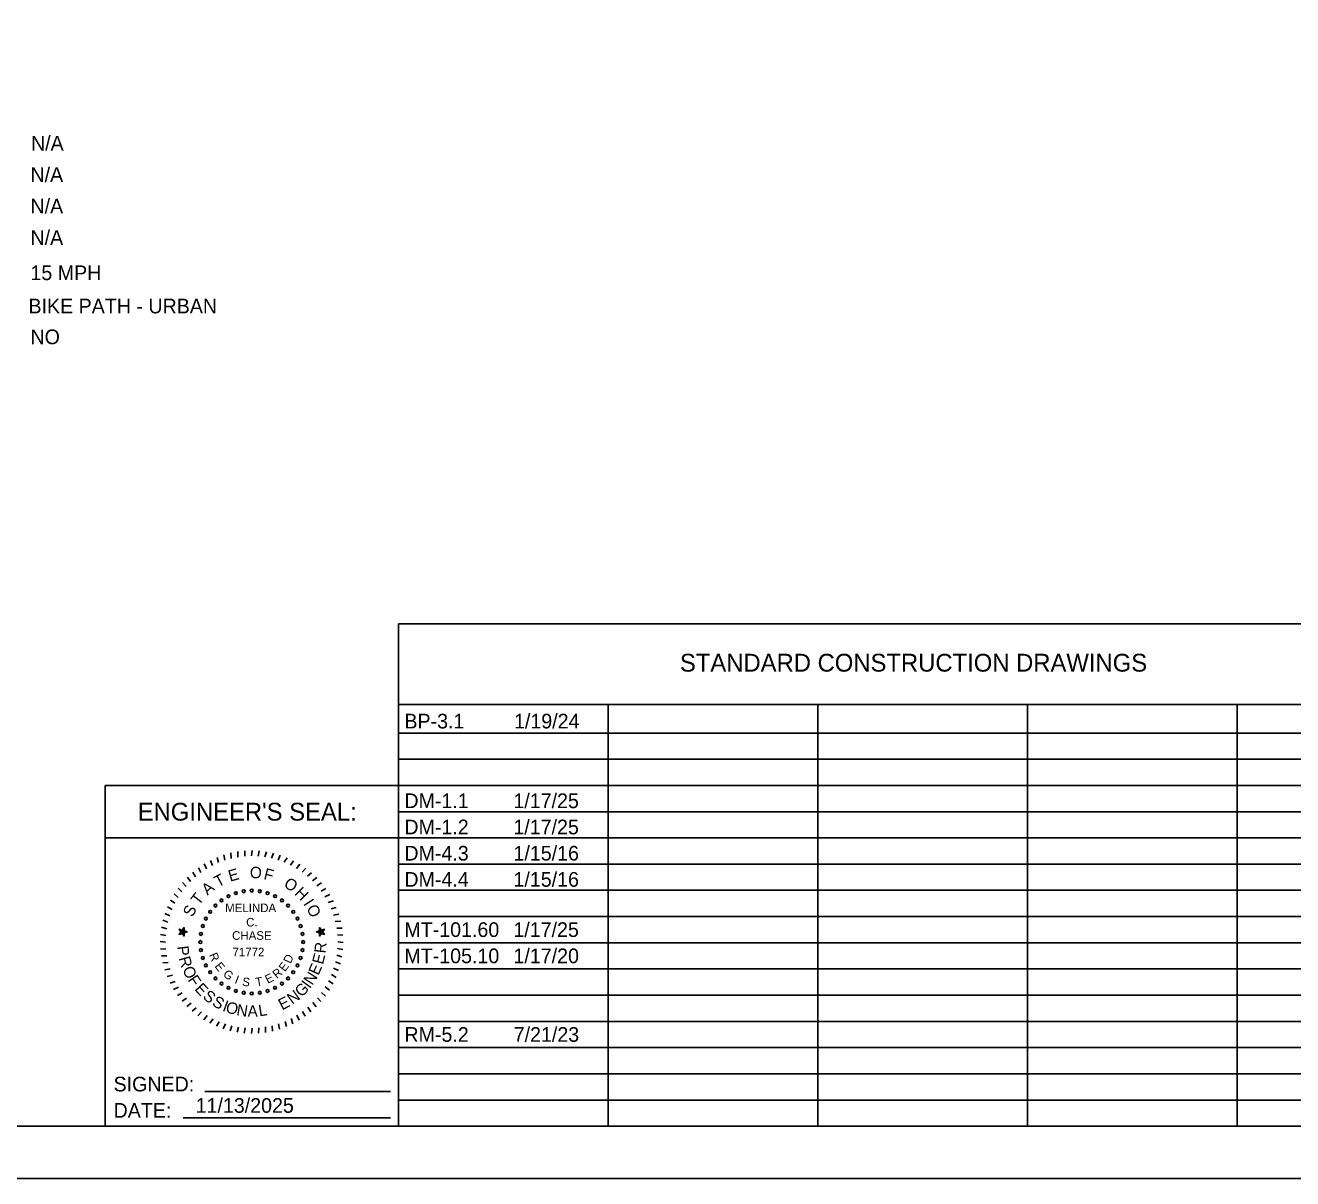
# Model space of a CAD drawing. Extents: x 0 to 34, y 0 to 22.
# Drawn here: x 7.69 to 19.78, y 0 to 11 of the extents above; entities that cross this region are included whole.
import ezdxf

# ---------------------------------------------------------------- set-up
doc = ezdxf.new("R2010")
doc.units = 0
for name, color, linetype in [('Default', 7, 'Continuous'), ('GM_X_Adjacent_County', 7, 'Continuous'), ('GM_X_County', 7, 'Continuous'), ('GM_X_Section', 7, 'Continuous'), ('GM_X_Township', 7, 'Continuous')]:
    doc.layers.add(name, color=color, linetype=linetype)

msp = doc.modelspace()

# ---------------------------------------------------------------- linework, layer by layer
at = {"layer": 'Default'}
for p, q in [((9.456, 3.036), (9.473, 2.987)), ((9.518, 3.064), (9.531, 3.014)), ((9.582, 3.087), (9.591, 3.037)), ((9.648, 3.106), (9.653, 3.055)), ((9.716, 3.119), (9.717, 3.067)), ((9.784, 3.127), (9.781, 3.075)), ((9.852, 3.129), (9.845, 3.078)), ((9.92, 3.126), (9.909, 3.076)), ((9.988, 3.118), (9.973, 3.068)), ((10.056, 3.104), (10.037, 3.056)), ((10.121, 3.085), (10.099, 3.039)), ((10.185, 3.061), (10.159, 3.017)), ((10.248, 3.032), (10.218, 2.99)), ((9.285, 2.922), (9.313, 2.879)), ((9.339, 2.965), (9.363, 2.919)), ((9.396, 3.002), (9.416, 2.955)), ((10.307, 2.999), (10.274, 2.959)), ((10.364, 2.96), (10.328, 2.923)), ((10.417, 2.918), (10.379, 2.884)), ((9.188, 2.826), (9.222, 2.788)), ((9.234, 2.876), (9.265, 2.835)), ((10.468, 2.871), (10.427, 2.84)), ((10.514, 2.821), (10.471, 2.793)), ((9.107, 2.716), (9.147, 2.683)), ((9.145, 2.772), (9.182, 2.737)), ((10.556, 2.767), (10.511, 2.742)), ((10.594, 2.709), (10.547, 2.689)), ((9.044, 2.594), (9.089, 2.568)), ((9.073, 2.656), (9.115, 2.627)), ((10.627, 2.65), (10.578, 2.633)), ((10.655, 2.587), (10.606, 2.574)), ((9.001, 2.464), (9.049, 2.445)), ((9.02, 2.53), (9.066, 2.507)), ((10.679, 2.523), (10.628, 2.514)), ((10.697, 2.457), (10.646, 2.452)), ((8.979, 2.329), (9.03, 2.318)), ((8.988, 2.397), (9.037, 2.382)), ((9.155, 2.33), (9.202, 2.394)), ((9.202, 2.314), (9.155, 2.379)), ((9.155, 2.379), (9.231, 2.354)), ((9.231, 2.354), (9.155, 2.33)), ((9.202, 2.394), (9.202, 2.314)), ((10.542, 2.379), (10.465, 2.354)), ((10.465, 2.354), (10.542, 2.33)), ((10.495, 2.394), (10.495, 2.314)), ((10.542, 2.33), (10.495, 2.394)), ((10.495, 2.314), (10.542, 2.379)), ((10.71, 2.39), (10.659, 2.389)), ((10.718, 2.322), (10.667, 2.325)), ((8.976, 2.261), (9.027, 2.254)), ((8.979, 2.192), (9.03, 2.189)), ((10.717, 2.185), (10.667, 2.196)), ((10.72, 2.253), (10.669, 2.26)), ((8.987, 2.124), (9.038, 2.125)), ((9, 2.057), (9.051, 2.062)), ((10.695, 2.05), (10.648, 2.069)), ((10.709, 2.117), (10.66, 2.132)), ((9.018, 1.991), (9.069, 2)), ((9.041, 1.927), (9.091, 1.94)), ((10.653, 1.92), (10.608, 1.946)), ((10.677, 1.984), (10.63, 2.006)), ((9.07, 1.864), (9.118, 1.881)), ((9.103, 1.804), (9.15, 1.825)), ((10.59, 1.798), (10.55, 1.831)), ((10.624, 1.858), (10.581, 1.887)), ((9.141, 1.747), (9.186, 1.772)), ((9.183, 1.693), (9.226, 1.721)), ((10.509, 1.688), (10.475, 1.726)), ((10.552, 1.741), (10.515, 1.777)), ((9.229, 1.643), (9.27, 1.674)), ((9.279, 1.596), (9.318, 1.63)), ((9.333, 1.554), (9.369, 1.591)), ((10.358, 1.549), (10.334, 1.595)), ((10.412, 1.592), (10.384, 1.635)), ((10.462, 1.638), (10.431, 1.679)), ((9.39, 1.515), (9.422, 1.555)), ((9.449, 1.482), (9.479, 1.524)), ((9.511, 1.453), (9.537, 1.497)), ((9.575, 1.429), (9.598, 1.475)), ((9.641, 1.41), (9.66, 1.458)), ((10.048, 1.408), (10.043, 1.459)), ((10.114, 1.427), (10.105, 1.477)), ((10.179, 1.45), (10.166, 1.5)), ((10.241, 1.478), (10.224, 1.527)), ((10.301, 1.512), (10.28, 1.559)), ((9.708, 1.396), (9.723, 1.446)), ((9.776, 1.388), (9.787, 1.438)), ((9.845, 1.385), (9.852, 1.436)), ((9.913, 1.387), (9.916, 1.439)), ((9.981, 1.395), (9.98, 1.447))]:
    msp.add_line(p, q, dxfattribs=at)
for points in [[(9.155, 2.33), (9.202, 2.394), (9.202, 2.345), (9.155, 2.33)], [(9.155, 2.33), (9.202, 2.345), (9.202, 2.394)], [(9.173, 2.354), (9.155, 2.379), (9.184, 2.37)], [(9.202, 2.345), (9.155, 2.33), (9.202, 2.345)], [(9.202, 2.394), (9.202, 2.394), (9.184, 2.339), (9.202, 2.314)], [(9.184, 2.37), (9.184, 2.37), (9.231, 2.354), (9.202, 2.364)], [(9.202, 2.364), (9.231, 2.354), (9.202, 2.345)], [(10.513, 2.37), (10.513, 2.37), (10.465, 2.354), (10.495, 2.364)], [(10.495, 2.364), (10.465, 2.354), (10.495, 2.345)], [(10.495, 2.394), (10.495, 2.394), (10.513, 2.339), (10.495, 2.314)], [(10.542, 2.33), (10.495, 2.345), (10.495, 2.394)], [(10.542, 2.33), (10.495, 2.394), (10.495, 2.345), (10.542, 2.33)], [(10.495, 2.345), (10.542, 2.33), (10.495, 2.345)], [(10.524, 2.354), (10.542, 2.379), (10.513, 2.37)]]:
    msp.add_lwpolyline(points, close=True, dxfattribs=at)
for centre in [(9.56, 2.654), (9.626, 2.694), (9.697, 2.723), (9.772, 2.741), (9.848, 2.747), (9.925, 2.741), (10, 2.723), (10.071, 2.694), (10.137, 2.654), (9.452, 2.545), (9.502, 2.604), (10.195, 2.604), (10.245, 2.545), (9.382, 2.409), (9.411, 2.48), (10.285, 2.48), (10.315, 2.409), (9.364, 2.334), (10.333, 2.334), (9.358, 2.257), (9.364, 2.18), (10.333, 2.18), (10.339, 2.257), (9.382, 2.105), (10.315, 2.105), (9.411, 2.034), (9.452, 1.969), (10.245, 1.969), (10.285, 2.034), (9.502, 1.91), (9.56, 1.86), (9.626, 1.82), (10.071, 1.82), (10.137, 1.86), (10.195, 1.91), (9.697, 1.79), (9.772, 1.773), (9.848, 1.766), (9.925, 1.773), (10, 1.79)]:
    msp.add_circle(centre, 0.0136, dxfattribs=at)
at = {"layer": 'GM_X_Adjacent_County'}
for p, q in [((9.401, 0.832), (11.171, 0.832)), ((9.193, 0.581), (11.171, 0.581))]:
    msp.add_line(p, q, dxfattribs=at)
at = {"layer": 'GM_X_County'}
msp.add_lwpolyline([(1.5, 21.5), (33.5, 21.5), (33.5, 0.5), (1.5, 0.5)], close=True, dxfattribs=at)
at = {"layer": 'GM_X_Section'}
msp.add_lwpolyline([(0, 0), (34, 0), (34, 22), (0, 22)], close=True, dxfattribs=at)
at = {"layer": 'GM_X_Township'}
for p, q in [((11.25, 5.292), (24.7, 5.292)), ((11.25, 0.5), (11.25, 5.292)), ((11.25, 4.521), (24.7, 4.521)), ((13.25, 0.5), (13.25, 4.521)), ((15.25, 0.5), (15.25, 4.521)), ((17.25, 0.5), (17.25, 4.521)), ((19.25, 0.5), (19.25, 4.521)), ((11.25, 4.25), (24.7, 4.25)), ((11.25, 4), (24.7, 4)), ((8.45, 0.5), (8.45, 3.75)), ((8.45, 3.75), (11.25, 3.75)), ((11.25, 3.75), (24.7, 3.75)), ((11.25, 3.5), (24.7, 3.5)), ((8.45, 3.25), (11.25, 3.25)), ((11.25, 3.25), (24.7, 3.25)), ((11.25, 3), (24.7, 3)), ((11.25, 2.75), (24.7, 2.75)), ((11.25, 2.5), (24.7, 2.5)), ((11.25, 2.25), (24.7, 2.25)), ((11.25, 2), (24.7, 2)), ((11.25, 1.75), (24.7, 1.75)), ((11.25, 1.5), (24.7, 1.5)), ((11.25, 1.25), (24.7, 1.25)), ((11.25, 1), (24.7, 1)), ((11.25, 0.75), (24.7, 0.75))]:
    msp.add_line(p, q, dxfattribs=at)

# ---------------------------------------------------------------- texts
at = {"layer": 'Default'}
for s, height, rotation, p in [('T', 0.109, 27.9341, (9.527, 2.776)), ('E', 0.109, 15.9341, (9.642, 2.831)), ('O', 0.109, 358.0005, (9.829, 2.867)), ('F', 0.109, 346.0005, (9.956, 2.858)), ('A', 0.109, 39.9341, (9.426, 2.698)), ('O', 0.109, 326.9918, (10.146, 2.79)), ('H', 0.109, 314.9918, (10.25, 2.716)), ('T', 0.109, 51.9341, (9.344, 2.6)), ('I', 0.109, 302.9918, (10.337, 2.623)), ('S', 0.109, 63.9341, (9.284, 2.488)), ('O', 0.109, 297.986, (10.367, 2.579)), ('P', 0.109, 276.5049, (9.136, 2.215)), ('R', 0.109, 84.1986, (10.553, 2.146)), ('R', 0.109, 285.5049, (9.151, 2.104)), ('R', 0.0817, 292.3868, (9.439, 2.135)), ('E', 0.0818, 308.3846, (9.49, 2.025)), ('E', 0.0818, 52.9931, (10.164, 1.968)), ('D', 0.0817, 66.0008, (10.22, 2.045)), ('E', 0.109, 66.1986, (10.484, 1.933)), ('E', 0.109, 75.1986, (10.527, 2.037)), ('O', 0.109, 294.5049, (9.184, 1.997)), ('F', 0.109, 303.5049, (9.233, 1.896)), ('G', 0.0818, 324.4496, (9.568, 1.935)), ('I', 0.0817, 338.6934, (9.679, 1.866)), ('E', 0.0818, 26.4392, (10.001, 1.858)), ('R', 0.0818, 39.8183, (10.088, 1.903)), ('N', 0.109, 57.1986, (10.426, 1.838)), ('E', 0.109, 312.5049, (9.297, 1.805)), ('S', 0.0818, 352.5323, (9.754, 1.84)), ('T', 0.0818, 10, (9.892, 1.833)), ('G', 0.109, 45, (10.324, 1.725)), ('I', 0.109, 54, (10.402, 1.806)), ('S', 0.109, 321.5049, (9.374, 1.724)), ('S', 0.109, 330.5049, (9.463, 1.656)), ('I', 0.109, 339.5049, (9.562, 1.603)), ('E', 0.109, 27, (10.137, 1.604)), ('N', 0.109, 36, (10.235, 1.657)), ('O', 0.109, 342, (9.591, 1.592)), ('N', 0.109, 351, (9.698, 1.559)), ('L', 0.109, 9, (9.921, 1.547))]:
    msp.add_text(s, height=height, rotation=rotation, dxfattribs=at).set_placement(p)
for s, height, p in [('MELINDA', 0.0818, (9.595, 2.542)), ('C.', 0.0817, (9.795, 2.405)), ('CHASE', 0.0818, (9.661, 2.278)), ('71772', 0.0818, (9.665, 2.121)), ('A', 0.109, (9.809, 1.544)), ('11/13/2025', 0.14, (9.313, 0.628))]:
    msp.add_text(s, height=height, dxfattribs=at).set_placement(p)
at = {"layer": 'GM_X_Adjacent_County'}
for s, height, p in [('N/A', 0.14, (7.742, 9.806)), ('N/A', 0.14, (7.737, 9.506)), ('N/A', 0.14, (7.737, 9.206)), ('N/A', 0.14, (7.737, 8.906)), ('15 MPH', 0.14, (7.737, 8.57)), ('BIKE PATH - URBAN', 0.14, (7.718, 8.253)), ('NO', 0.14, (7.737, 7.959)), ('STANDARD CONSTRUCTION DRAWINGS', 0.17, (13.934, 4.836)), ('BP-3.1', 0.14, (11.305, 4.294)), ('1/19/24', 0.14, (12.351, 4.294)), ('DM-1.1', 0.14, (11.305, 3.534)), ('1/17/25', 0.14, (12.345, 3.534)), ("ENGINEER'S SEAL:", 0.17, (8.76, 3.415)), ('DM-1.2', 0.14, (11.305, 3.284)), ('1/17/25', 0.14, (12.345, 3.284)), ('DM-4.3', 0.14, (11.305, 3.034)), ('1/15/16', 0.14, (12.346, 3.034)), ('DM-4.4', 0.14, (11.305, 2.784)), ('1/15/16', 0.14, (12.346, 2.784)), ('MT-101.60', 0.14, (11.305, 2.305)), ('1/17/25', 0.14, (12.345, 2.305)), ('MT-105.10', 0.14, (11.305, 2.055)), ('1/17/20', 0.14, (12.346, 2.055)), ('7/21/23', 0.14, (12.348, 1.305)), ('RM-5.2', 0.14, (11.305, 1.305)), ('SIGNED:', 0.14, (8.53, 0.832)), ('DATE:', 0.14, (8.53, 0.581))]:
    msp.add_text(s, height=height, dxfattribs=at).set_placement(p)

doc.saveas('drawing.dxf')
